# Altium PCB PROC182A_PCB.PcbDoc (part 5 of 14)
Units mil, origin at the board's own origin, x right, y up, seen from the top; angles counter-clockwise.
Board outline 3168.31 x 3700.79 mil, 8 copper layers (Top Layer, L2_GND1, L3_SIG1, L4_PWR1, L5_PWR2, L6_SIG2, L7_GND2, Bottom Layer), stack 58.1 mil thick; 580 components, 391 nets, 8314 pads, 4370 vias.
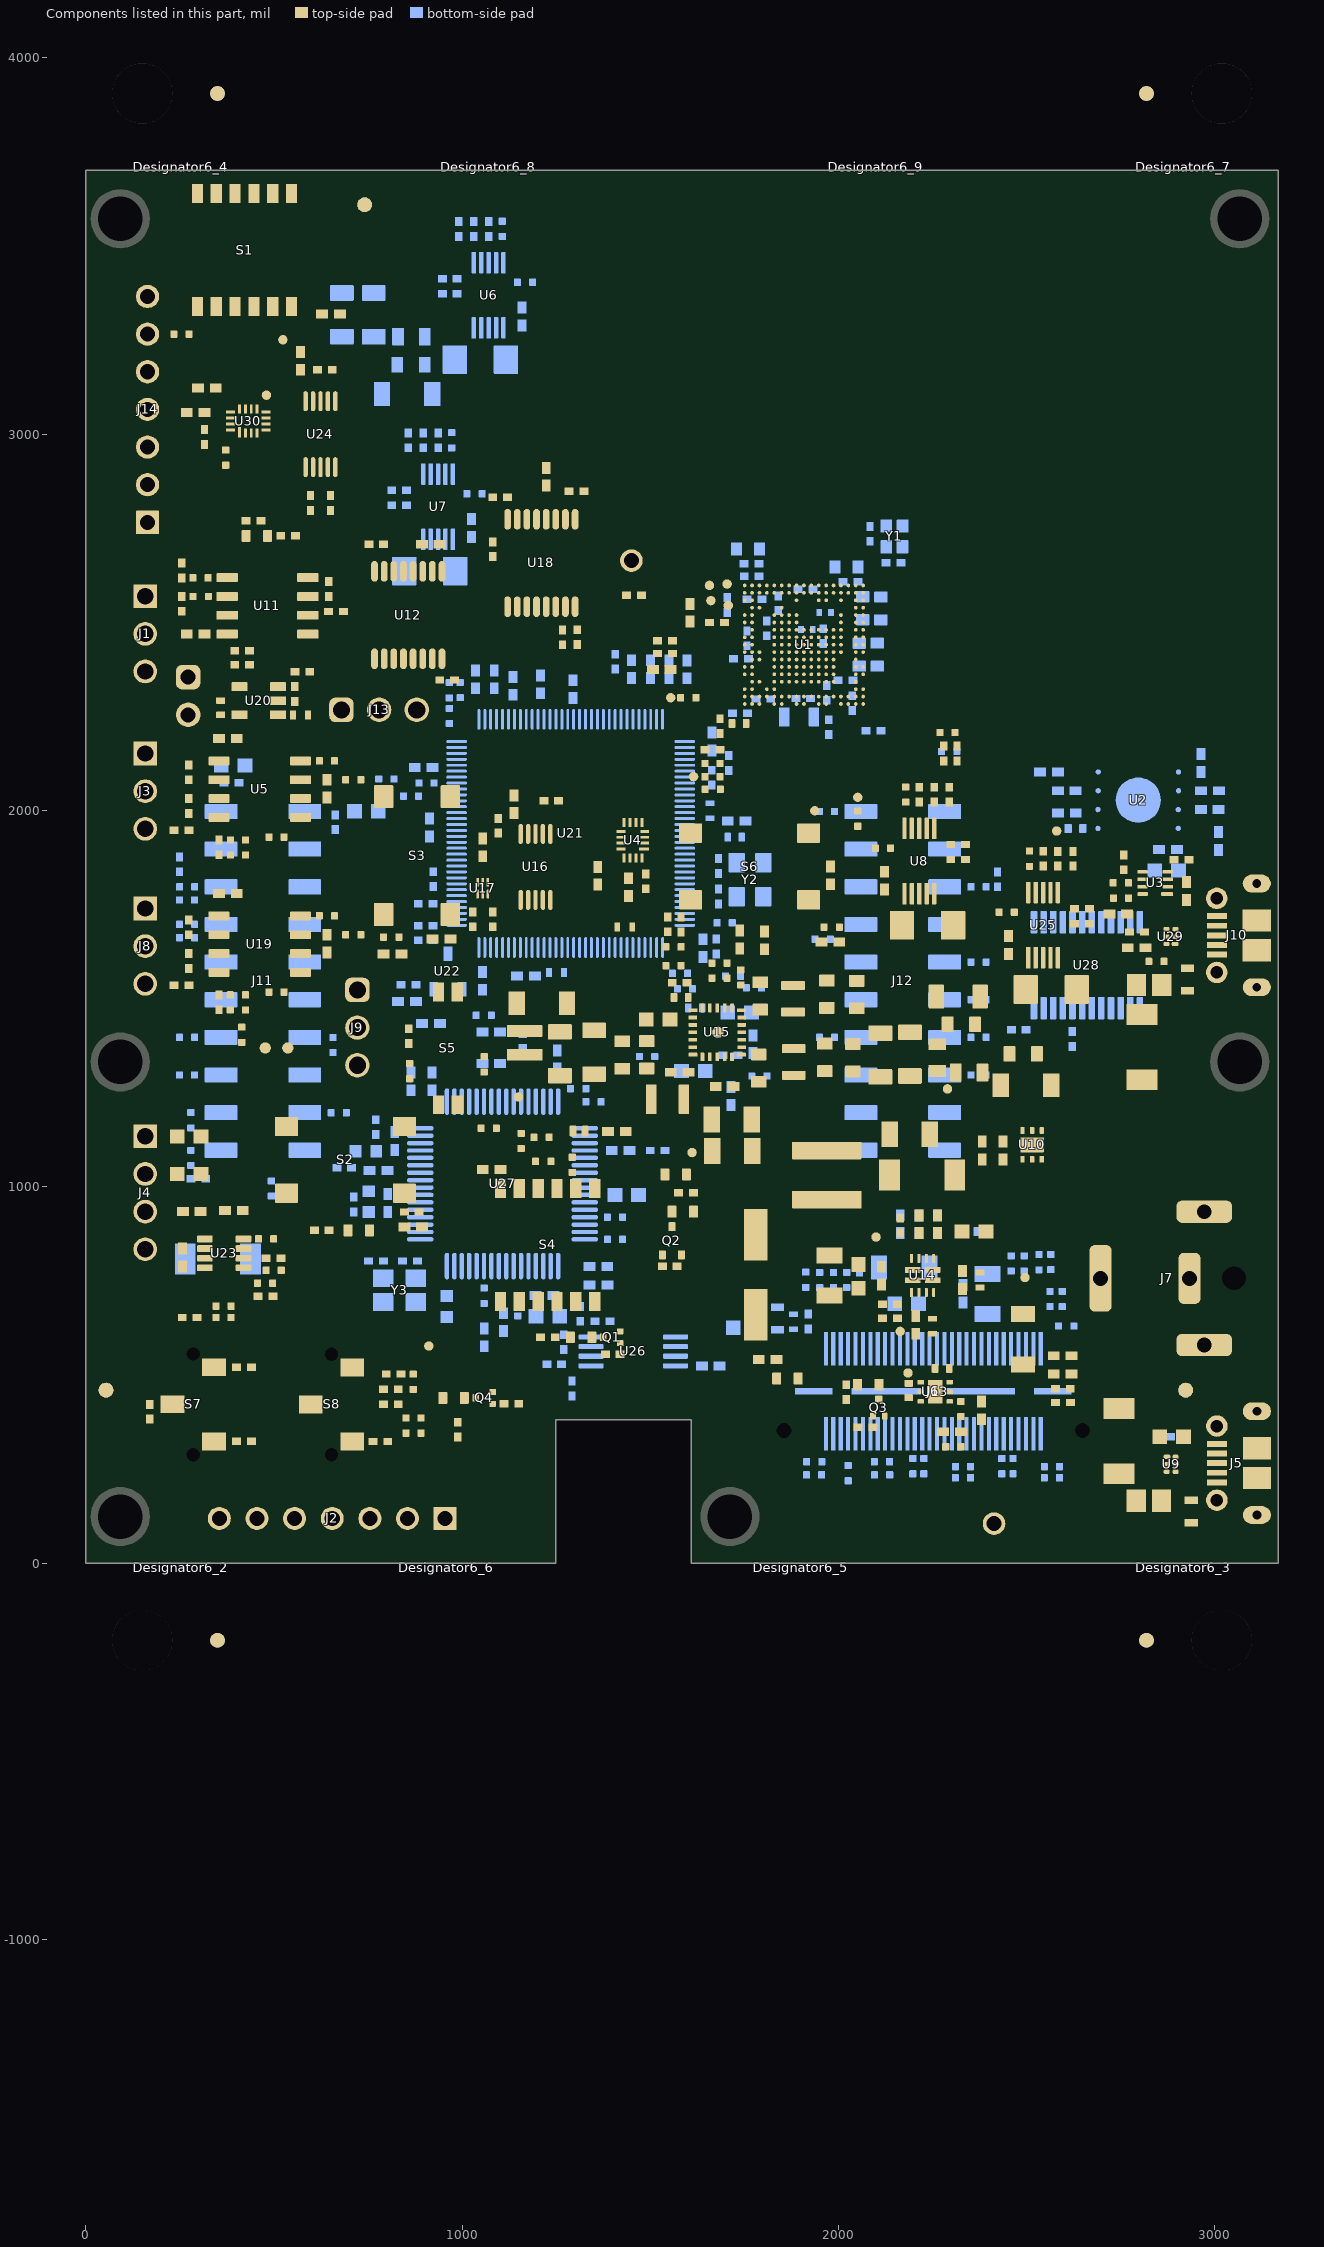
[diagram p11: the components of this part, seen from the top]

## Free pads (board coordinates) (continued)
  round 6 on Mech16: 1(205.76,1382.76) 1(205.76,1382.76) 1(205.76,1414.25) 1(205.76,1414.25) 1(209.78,1279.76) 1(209.78,1279.76) 1(209.78,1311.25) 1(209.78,1311.25) 1(218.77,1080.76) 1(218.77,1080.76) 1(218.77,1112.25) 1(218.77,1112.25) 1(220.77,1182.76) 1(220.77,1182.76) 1(220.77,1214.25) 1(220.77,1214.25) 1(226.29,1382.76) 1(226.29,1414.25) 1(230.3,1279.76) 1(230.3,1311.25) 1(239.3,1080.76) 1(239.3,1112.25) 1(241.3,1182.76) 1(241.3,1214.25) 1(244.29,1382.76) 1(244.29,1414.25) 1(248.3,1279.76) 1(248.3,1311.25) 1(250.83,-300.02) 1(251.83,-250.02) 1(253.83,-248.02) 1(253.83,-248.02) 1(253.83,-200.02) 1(253.83,-200.02) 1(257.3,1080.76) 1(257.3,1112.25) 1(259.3,1182.76) 1(259.3,1214.25) 1(264.82,1382.76) 1(264.82,1382.76) 1(264.82,1414.25) 1(264.82,1414.25) 1(264.83,-300.02) 1(264.83,-300.02) 1(264.83,-189.02) 1(268.83,1279.76) 1(268.83,1279.76) 1(268.83,1311.25) 1(268.83,1311.25) 1(277.82,1080.76) 1(277.82,1080.76) 1(277.82,1112.25) 1(277.82,1112.25) 1(279.82,1182.76) 1(279.82,1182.76) 1(279.82,1214.25) 1(279.82,1214.25) 1(279.83,-285.02) 1(330.55,580.99) 1(330.55,580.99) 1(330.55,601.51) 1(330.55,619.51) 1(330.55,640.04) 1(330.55,640.04) 1(333.83,558.98) 1(362.04,580.99) 1(362.04,580.99) 1(362.04,601.51) 1(362.04,619.51) 1(362.04,640.04) 1(362.04,640.04) 1(365.83,558.98) 1(365.83,558.98) 1(366.83,559.98) 1(434.92,412.58) 1(434.92,412.58) 1(434.92,433.11) 1(434.92,451.11) 1(434.92,471.64) 1(434.92,471.64) 1(434.92,482.58) 1(434.92,482.58) 1(434.92,503.11) 1(434.92,521.11) 1(434.92,541.64) 1(434.92,541.64) 1(466.41,412.58) 1(466.41,412.58) 1(466.41,433.11) 1(466.41,451.11) 1(466.41,471.64) 1(466.41,471.64) 1(466.41,482.58) 1(466.41,482.58) 1(466.41,503.11) 1(466.41,521.11) 1(466.41,541.64) 1(466.41,541.64) 1(559.67,2131.41) 1(559.67,2131.41) 1(559.67,2623.45) 1(559.67,2623.45) 1(567.11,2139.01) 1(567.11,2139.01) 1(567.11,2313.41) 1(567.11,2313.41) 1(567.19,2138.93) 1(567.19,2138.93) 1(567.19,2313.37) 1(567.19,2313.37) 1(606.03,2573.97) 1(606.03,2573.97) 1(607.91,2580.81) 1(607.91,2580.81) 1(608.03,2565.25) 1(608.03,2565.25) 1(608.07,2581.05) 1(608.07,2581.05) 1(608.15,2195.33) 1(608.15,2195.33) 1(608.15,2212.25) 1(608.15,2212.25) 1(610.27,2195.33) 1(610.27,2195.33) 1(610.27,2209.37) 1(610.27,2209.37) 1(610.35,2209.37) 1(610.35,2209.37) 1(611.23,2212.25) 1(611.23,2212.25) 1(611.51,2572.69) 1(611.51,2572.69) 1(612.39,2577.85) 1(612.39,2577.85) 1(612.47,2578.01) 1(612.47,2578.01) 1(612.99,2567.25) 1(612.99,2567.25) 1(613.71,2585.25) 1(613.71,2585.25) 1(615.63,2195.33) 1(615.63,2195.33) 1(616.59,2198.01) 1(616.59,2198.01) 1(616.91,2580.65) 1(616.91,2580.65) 1(617.51,2195.33) 1(617.51,2195.33) 1(617.67,2558.53) 1(617.67,2558.53) 1(619.99,2546.33) 1(619.99,2546.33) 1(621.91,2212.25) 1(621.91,2212.25) 1(622.55,2581.25) 1(622.55,2581.25) 1(622.59,2586.61) 1(622.59,2586.61) 1(622.83,2209.37) 1(622.83,2209.37) 1(622.87,2195.33) 1(622.87,2195.33) 1(622.87,2209.37) 1(622.87,2209.37) 1(624.99,2195.33) 1(624.99,2195.33) 1(624.99,2212.25) 1(624.99,2212.25) 1(625.03,2548.57) 1(625.03,2548.57) 1(626.87,2210.33) 1(626.87,2210.33) 1(626.87,2212.25) 1(626.87,2212.25) 1(632.55,2195.33) 1(632.55,2195.33) 1(632.55,2210.33) 1(632.55,2210.33) 1(632.55,2580.05) 1(632.55,2580.05) 1(632.67,2585.49) 1(632.67,2585.49) 1(634.75,2537.77) 1(634.75,2537.77) 1(634.79,2195.33) 1(634.79,2195.33) 1(634.79,2210.33) 1(634.79,2210.33) 1(640.43,2210.33) 1(640.43,2210.33) 1(640.43,2212.25) 1(640.43,2212.25) 1(640.51,2524.73) 1(640.51,2524.73) 1(641.07,2241.77) 1(641.07,2241.77) 1(641.07,2262.17) 1(641.07,2262.17) 1(641.83,2266.57) 1(641.83,2266.57) 1(643.11,2172.81) 1(643.11,2172.81) 1(643.11,2213.81) 1(643.11,2213.81) 1(643.95,2269.73) 1(643.95,2269.73) 1(644.55,2582.41) 1(644.55,2582.41) 1(644.67,2576.77) 1(644.67,2576.77) 1(646.59,2526.41) 1(646.59,2526.41) 1(647.23,2271.65) 1(647.23,2271.65) 1(647.63,2241.77) 1(647.63,2241.77) 1(647.63,2260.45) 1(647.63,2260.45) 1(649.15,2265.53) 1(649.15,2265.53) 1(650.23,2537.73) 1(650.23,2537.73) 1(650.71,2172.81) 1(650.71,2172.81) 1(650.71,2176.05) 1(650.71,2176.05) 1(650.83,2176.05) 1(650.83,2176.05) 1(651.03,2188.25) 1(651.03,2188.25) 1(651.03,2200.85) 1(651.03,2200.85) 1(651.03,2213.81) 1(651.03,2213.81) 1(651.13,-803.95) 1(651.15,2200.85) 1(651.15,2200.85) 1(651.23,2183.85) 1(651.23,2183.85) 1(651.23,2192.69) 1(651.23,2192.69) 1(651.63,2272.29) 1(651.63,2272.29) 1(651.83,2180.65) 1(651.83,2180.65) 1(651.83,2195.85) 1(651.83,2195.85) 1(653.11,2178.73) 1(653.11,2178.73) 1(653.11,2197.77) 1(653.11,2197.77) 1(653.43,2267.13) 1(653.43,2267.13) 1(653.83,2172.97) 1(653.83,2172.97) 1(653.99,2203.61) 1(653.99,2203.61) 1(655.27,2178.09) 1(655.27,2178.09) 1(655.27,2198.41) 1(655.27,2198.41) 1(656.43,2266.53) 1(656.43,2266.53) 1(656.63,2548.89) 1(656.63,2548.89) 1(656.91,2270.97) 1(656.91,2270.97) 1(657.35,2178.73) 1(657.35,2178.73) 1(657.35,2197.77) 1(657.35,2197.77) 1(657.83,2171.97) 1(657.83,2171.97) 1(657.83,2204.49) 1(657.83,2204.49) 1(657.87,2577.61) 1(657.87,2577.61) 1(658.51,2571.57) 1(658.51,2571.57) 1(658.63,2180.65) 1(658.63,2180.65) 1(658.63,2195.85) 1(658.63,2195.85) 1(658.67,2264.85) 1(658.67,2264.85) 1(659.23,2183.81) 1(659.23,2183.81) 1(659.23,2192.69) 1(659.23,2192.69) 1(659.39,2188.25) 1(659.39,2188.25) 1(660.11,2262.37) 1(660.11,2262.37) 1(660.3,-818.55) 1(660.3,-813.12) 1(660.3,-813.12) 1(660.51,2267.57) 1(660.51,2267.57) 1(660.63,2241.77) 1(660.63,2241.77) 1(660.63,2259.29) 1(660.63,2259.29) 1(660.63,2267.57) 1(660.63,2267.57) 1(660.63,2282.81) 1(660.63,2282.81) 1(662.07,2172.89) 1(662.07,2172.89) 1(662.07,2203.57) 1(662.07,2203.57) 1(664.79,2558.37) 1(664.79,2558.37) 1(665.03,2175.81) 1(665.03,2175.81) 1(665.03,2200.69) 1(665.03,2200.69) 1(666.75,2180.85) 1(666.75,2180.85) 1(666.75,2195.65) 1(666.75,2195.65) 1(666.83,2502.89) 1(666.83,2502.89) 1(667.19,2241.77) 1(667.19,2241.77) 1(667.19,2282.81) 1(667.19,2282.81) 1(667.31,2188.25) 1(667.31,2188.25) 1(671.83,2172.81) 1(671.83,2172.81) 1(672.19,2571.25) 1(672.19,2571.25) 1(672.43,2241.81) 1(672.43,2241.81) 1(672.43,2246.89) 1(672.43,2246.89) 1(672.43,2266.61) 1(672.43,2266.61) 1(672.43,2271.49) 1(672.43,2271.49) 1(672.59,2175.37) 1(672.59,2175.37) 1(672.79,2178.77) 1(672.79,2178.77) 1(672.79,2195.05) 1(672.79,2195.05) 1(673.19,2198.85) 1(673.19,2198.85) 1(673.63,2564.61) 1(673.63,2564.61) 1(674.87,2201.85) 1(674.87,2201.85) 1(675.19,2246.65) 1(675.19,2246.65) 1(676.67,2241.49) 1(676.67,2241.49) 1(677.87,2247.69) 1(677.87,2247.69) 1(678.27,2203.81) 1(678.27,2203.81) 1(678.35,2250.73) 1(678.35,2250.73) 1(678.35,2266.61) 1(678.35,2266.61) 1(678.35,2271.49) 1(678.35,2271.49) 1(678.35,2280.41) 1(678.35,2280.41) 1(679.39,2172.81) 1(679.39,2172.81) 1(680.39,2176.01) 1(680.39,2176.01) 1(680.39,2182.17) 1(680.39,2182.17) 1(680.39,2188.25) 1(680.39,2188.25) 1(680.39,2195.33) 1(680.39,2195.33) 1(680.47,2176.01) 1(680.47,2176.01) 1(680.83,2241.97) 1(680.83,2241.97) 1(681.07,2192.97) 1(681.07,2192.97) 1(681.23,2198.09) 1(681.23,2198.09) 1(682.03,2178.49) 1(682.03,2178.49) 1(683.31,2243.45) 1(683.31,2243.45) 1(683.47,2497.61) 1(683.47,2497.61) 1(683.51,2191.69) 1(683.51,2191.69) 1(683.67,2172.81) 1(683.67,2172.81) 1(683.75,2186.69) 1(683.75,2186.69) 1(683.99,2204.49) 1(683.99,2204.49) 1(684.03,2199.09) 1(684.03,2199.09) 1(684.51,2245.81) 1(684.51,2245.81) 1(684.87,2249.09) 1(684.87,2249.09) 1(684.87,2266.61) 1(684.87,2266.61) 1(684.87,2271.49) 1(684.87,2271.49) 1(684.87,2280.41) 1(684.87,2280.41) 1(685.27,2177.37) 1(685.27,2177.37) 1(686.79,2198.01) 1(686.79,2198.01) 1(686.79,2510.65) 1(686.79,2510.65) 1(687.07,2563.57) 1(687.07,2563.57) 1(687.23,2184.97) 1(687.23,2184.97) 1(687.55,2178.65) 1(687.55,2178.65) 1(687.71,2194.25) 1(687.71,2194.25) 1(687.71,2195.09) 1(687.71,2195.09) 1(688.03,2190.49) 1(688.03,2190.49) 1(688.23,2181.69) 1(688.23,2181.69) 1(688.23,2204.01) 1(688.23,2204.01) 1(688.35,2171.97) 1(688.35,2171.97) 1(689.83,2266.61) 1(689.83,2266.61) 1(689.83,2271.49) 1(689.83,2271.49) 1(691.55,2189.17) 1(691.55,2189.17) 1(691.67,2202.41) 1(691.67,2202.41) 1(691.87,2172.77) 1(691.87,2172.77) 1(693.95,2187.29) 1(693.95,2187.29) 1(693.99,2199.49) 1(693.99,2199.49) 1(694.15,2174.85) 1(694.15,2174.85) 1(694.15,2523.77) 1(694.15,2523.77) 1(694.47,2241.77) 1(694.47,2241.77) 1(694.47,2271.49) 1(694.47,2271.49) 1(694.47,2276.61) 1(694.47,2276.61) 1(694.47,2282.81) 1(694.47,2282.81) 1(694.83,2194.25) 1(694.83,2194.25) 1(694.83,2194.97) 1(694.83,2194.97) 1(695.39,2184.57) 1(695.39,2184.57) 1(695.43,2177.73) 1(695.43,2177.73) 1(695.83,567.22) 1(695.83,567.22) 1(695.83,575.98) 1(695.83,2180.85) 1(695.83,2180.85) 1(696.15,2483.29) 1(696.15,2483.29) 1(696.75,2201.53) 1(696.75,2201.53) 1(697.35,2206.05) 1(697.35,2206.05) 1(697.71,2196.01) 1(697.71,2196.01) 1(699.23,2209.97) 1(699.23,2209.97) 1(700.19,2480.93) 1(700.19,2480.93) 1(700.35,2192.17) 1(700.35,2192.17) 1(701.03,2241.77) 1(701.03,2241.77) 1(701.03,2271.49) 1(701.03,2271.49) 1(701.03,2276.61) 1(701.03,2276.61) 1(701.03,2282.81) 1(701.03,2282.81) 1(702.15,2554.81) 1(702.15,2554.81) 1(702.71,2212.77) 1(702.71,2212.77) 1(702.92,560.13) 1(703.07,2461.61) 1(703.07,2461.61) 1(703.87,2534.53) 1(703.87,2534.53) 1(704.47,2189.93) 1(704.47,2189.93) 1(705.03,2201.41) 1(705.03,2201.41) 1(705.95,2271.49) 1(705.95,2271.49) 1(706.03,2508.01) 1(706.03,2508.01) 1(706.35,2206.09) 1(706.35,2206.09) 1(706.55,2196.77) 1(706.55,2196.77) 1(707.19,2462.29) 1(707.19,2462.29) 1(707.91,1266.46) 1(707.91,1266.46) 1(707.91,1266.46) 1(708.03,2213.81) 1(708.03,2213.81) 1(709.79,2189.17) 1(709.79,2189.17) 1(710.55,2195.25) 1(710.55,2195.25) 1(710.79,2207.73) 1(710.79,2207.73) 1(711.83,2516.53) 1(711.83,2516.53) 1(712.59,2271.49) 1(712.59,2271.49) 1(713.59,2541.05) 1(713.59,2541.05) 1(714.23,2172.81) 1(714.23,2172.81) 1(714.23,2189.17) 1(714.23,2189.17) 1(714.23,2195.25) 1(714.23,2195.25) 1(714.23,2207.73) 1(714.23,2207.73) 1(714.27,2540.49) 1(714.27,2540.49) 1(715.23,2241.77) 1(715.23,2241.77) 1(716.23,2478.45) 1(716.23,2478.45) 1(716.41,1257.96) 1(716.41,1257.96) 1(716.41,1274.96) 1(716.41,1274.96) 1(716.95,2545.13) 1(716.95,2545.13) 1(718.47,2444.09) 1(718.47,2444.09) 1(718.63,2249.29) 1(718.63,2249.29) 1(718.75,2249.29) 1(718.75,2249.29) 1(718.93,-820.55) 1(718.93,-809.55) 1(718.93,-809.55) 1(718.93,-809.55) 1(721.83,2470.01) 1(721.83,2470.01) 1(721.95,2241.77) 1(721.95,2241.77) 1(722.51,2172.81) 1(722.51,2172.81) 1(722.51,2213.81) 1(722.51,2213.81) 1(723.75,2444.69) 1(723.75,2444.69) 1(724.11,2271.49) 1(724.11,2271.49) 1(727.47,2263.85) 1(727.47,2263.85) 1(727.59,2263.85) 1(727.59,2263.85) 1(729.71,2172.81) 1(729.71,2172.81) 1(729.71,2195.73) 1(729.71,2195.73) 1(730.23,2199.65) 1(730.23,2199.65) 1(730.71,2271.49) 1(730.71,2271.49) 1(731.15,2534.77) 1(731.15,2534.77) 1(731.79,2202.41) 1(731.79,2202.41) 1(733.07,2241.77) 1(733.07,2241.77) 1(734.27,2204.01) 1(734.27,2204.01) 1(734.83,2531.89) 1(734.83,2531.89) 1(735.95,2436.17) 1(735.95,2436.17) 1(736.27,2249.29) 1(736.27,2249.29) 1(736.39,2249.29) 1(736.39,2249.29) 1(737.59,2204.49) 1(737.59,2204.49) 1(737.63,2172.81) 1(737.63,2172.81) 1(737.63,2194.09) 1(737.63,2194.09) 1(737.71,2430.69) 1(737.71,2430.69) 1(737.87,2450.13) 1(737.87,2450.13) 1(738.43,2197.41) 1(738.43,2197.41) 1(738.67,2456.37) 1(738.67,2456.37) 1(739.11,2444.41) 1(739.11,2444.41) 1(739.95,2241.77) 1(739.95,2241.77) 1(741.03,2198.41) 1(741.03,2198.41) 1(741.71,2450.29) 1(741.71,2450.29) 1(741.75,2439.65) 1(741.75,2439.65) 1(742.03,2203.53) 1(742.03,2203.53) 1(742.19,2271.49) 1(742.19,2271.49) 1(742.23,2462.61) 1(742.23,2462.61) 1(742.27,2462.65) 1(742.27,2462.65) 1(742.35,2455.25) 1(742.35,2455.25) 1(742.47,2536.97) 1(742.47,2536.97) 1(742.71,2445.73) 1(742.71,2445.73) 1(743.19,2437.69) 1(743.19,2437.69) 1(743.23,2517.77) 1(743.23,2517.77) 1(744.15,2197.17) 1(744.15,2197.17) 1(744.79,2441.93) 1(744.79,2441.93) 1(745.11,2200.57) 1(745.11,2200.57) 1(745.19,2460.17) 1(745.19,2460.17) 1(745.23,2172.81) 1(745.23,2172.81) 1(745.23,2193.29) 1(745.23,2193.29) 1(745.23,2200.57) 1(745.23,2200.57) 1(745.23,2213.81) 1(745.23,2213.81) 1(745.31,2460.33) 1(745.31,2460.33) 1(745.47,2467.37) 1(745.47,2467.37) 1(746.27,2433.49) 1(746.27,2433.49) 1(746.27,2439.93) 1(746.27,2439.93) 1(749.15,2271.49) 1(749.15,2271.49) 1(750.15,2428.41) 1(750.15,2428.41) 1(751.55,2432.85) 1(751.55,2432.85) 1(752.51,2477.69) 1(752.51,2477.69) 1(752.99,2515.81) 1(752.99,2515.81) 1(753.15,2172.81) 1(753.15,2172.81) 1(753.15,2213.81) 1(753.15,2213.81) 1(753.87,2536.33) 1(753.87,2536.33) 1(754.75,2532.21) 1(754.75,2532.21) 1(755.71,2475.61) 1(755.71,2475.61) 1(756.15,2421.41) 1(756.15,2421.41) 1(757.11,2484.49) 1(757.11,2484.49) 1(757.83,2184.61) 1(757.83,2184.61) 1(757.83,2192.57) 1(757.83,2192.57) 1(758.35,2424.45) 1(758.35,2424.45) 1(758.47,2179.25) 1(758.47,2179.25) 1(758.51,2197.49) 1(758.51,2197.49) 1(760.23,2482.25) 1(760.23,2482.25) 1(760.55,2175.25) 1(760.55,2175.25) 1(760.63,2201.25) 1(760.63,2201.25) 1(760.91,2453.17) 1(760.91,2453.17) 1(764.03,2455.37) 1(764.03,2455.37) 1(764.07,2203.65) 1(764.07,2203.65) 1(764.07,2494.77) 1(764.07,2494.77) 1(764.19,2172.81) 1(764.19,2172.81) 1(765.03,2533.29) 1(765.03,2533.29) 1(765.39,2184.61) 1(765.39,2184.61) 1(765.39,2192.57) 1(765.39,2192.57) 1(766.07,2196.77) 1(766.07,2196.77) 1(766.31,2179.13) 1(766.31,2179.13) 1(767.31,2499.45) 1(767.31,2499.45) 1(767.35,2499.49) 1(767.35,2499.49) 1(768.47,2250.61) 1(768.47,2250.61) 1(768.87,2204.49) 1(768.87,2204.49) 1(768.95,2198.77) 1(768.95,2198.77) 1(769.23,2177.37) 1(769.23,2177.37) 1(769.31,2254.29) 1(769.31,2254.29) 1(769.47,2263.17) 1(769.47,2263.17) 1(769.59,2171.97) 1(769.59,2171.97) 1(769.71,2246.13) 1(769.71,2246.13) 1(770.67,2497.65) 1(770.67,2497.65) 1(770.87,2267.37) 1(770.87,2267.37) 1(771.31,2198.13) 1(771.31,2198.13) 1(771.43,2178.01) 1(771.43,2178.01) 1(771.51,2256.77) 1(771.51,2256.77) 1(771.83,2505.13) 1(771.83,2505.13) 1(772.71,2179.93) 1(772.71,2179.93) 1(772.71,2196.17) 1(772.71,2196.17) 1(772.79,2243.17) 1(772.79,2243.17) 1(773.35,2183.29) 1(773.35,2183.29) 1(773.35,2192.85) 1(773.35,2192.85) 1(773.51,2188.17) 1(773.51,2188.17) 1(773.67,2270.21) 1(773.67,2270.21) 1(773.95,2203.77) 1(773.95,2203.77) 1(774.23,2502.13) 1(774.23,2502.13) 1(774.55,2258.33) 1(774.55,2258.33) 1(774.79,2172.77) 1(774.79,2172.77) 1(775.03,2250.05) 1(775.03,2250.05) 1(775.63,2248.01) 1(775.63,2248.01) 1(775.83,2528.45) 1(775.83,2528.45) 1(775.95,2252.13) 1(775.95,2252.13) 1(776.27,2263.17) 1(776.27,2263.17) 1(776.35,2478.33) 1(776.35,2478.33) 1(776.59,2478.21) 1(776.59,2478.21) 1(777.11,2241.49) 1(777.11,2241.49) 1(777.19,2523.29) 1(777.19,2523.29) 1(777.31,2508.17) 1(777.31,2508.17) 1(777.35,2246.85) 1(777.35,2246.85) 1(777.47,2271.81) 1(777.47,2271.81) 1(777.79,2437.05) 1(777.79,2437.05) 1(777.87,2481.81) 1(777.87,2481.81) 1(777.91,2201.13) 1(777.91,2201.13) 1(778.07,2259.29) 1(778.07,2259.29) 1(778.07,2481.73) 1(778.07,2481.73) 1(778.15,2253.41) 1(778.15,2253.41) 1(778.43,2266.29) 1(778.43,2266.29) 1(778.47,2175.45) 1(778.47,2175.45) 1(778.59,2504.53) 1(778.59,2504.53) 1(779.55,2246.29) 1(779.55,2246.29) 1(780.51,2196.13) 1(780.51,2196.13) 1(780.71,2180.49) 1(780.71,2180.49) 1(781.23,2254.25) 1(781.23,2254.25) 1(781.43,2188.25) 1(781.43,2188.25) 1(781.63,2246.13) 1(781.63,2246.13) 1(781.63,2260.05) 1(781.63,2260.05) 1(781.75,2240.97) 1(781.75,2240.97) 1(781.87,2272.29) 1(781.87,2272.29) 1(782.31,2267.13) 1(782.31,2267.13) 1(782.39,2458.25) 1(782.39,2458.25) 1(783.11,2509.09) 1(783.11,2509.09) 1(783.23,2505.29) 1(783.23,2505.29) 1(784.71,2260.89) 1(784.71,2260.89) 1(784.75,2255.01) 1(784.75,2255.01) 1(785.43,2450.85) 1(785.43,2450.85) 1(785.75,2266.57) 1(785.75,2266.57) 1(785.99,2522.33) 1(785.99,2522.33) 1(786.07,2271.89) 1(786.07,2271.89) 1(786.11,2172.81) 1(786.11,2172.81) 1(786.11,2195.73) 1(786.11,2195.73) 1(786.19,2247.29) 1(786.19,2247.29) 1(786.23,2463.85) 1(786.23,2463.85) 1(786.63,2199.65) 1(786.63,2199.65) 1(786.91,2262.13) 1(786.91,2262.13) 1(786.95,2241.61) 1(786.95,2241.61) 1(787.51,2504.69) 1(787.51,2504.69) 1(787.71,2264.09) 1(787.71,2264.09) 1(788.19,2202.41) 1(788.19,2202.41) 1(788.27,2255.97) 1(788.27,2255.97) 1(788.35,2251.29) 1(788.35,2251.29) 1(788.35,2251.33) 1(788.35,2251.33) 1(788.43,2453.21) 1(788.43,2453.21) 1(788.51,2508.41) 1(788.51,2508.41) 1(789.03,2418.17) 1(789.03,2418.17) 1(789.59,2515.09) 1(789.59,2515.09) 1(789.87,2472.45) 1(789.87,2472.45) 1(789.91,2504.09) 1(789.91,2504.09) 1(790.11,2270.49) 1(790.11,2270.49) 1(790.63,2204.01) 1(790.63,2204.01) 1(790.87,2507.81) 1(790.87,2507.81) 1(791.11,2243.53) 1(791.11,2243.53) 1(791.31,2257.53) 1(791.31,2257.53) 1(791.47,2475.93) 1(791.47,2475.93) 1(791.99,2420.77) 1(791.99,2420.77) 1(793.11,2267.85) 1(793.11,2267.85) 1(793.47,2260.01) 1(793.47,2260.01) 1(793.87,2246.73) 1(793.87,2246.73) 1(793.95,2204.49) 1(793.95,2204.49) 1(794.03,2172.81) 1(794.03,2172.81) 1(794.03,2194.09) 1(794.03,2194.09) 1(794.27,2263.77) 1(794.27,2263.77) 1(794.83,2197.41) 1(794.83,2197.41) 1(794.95,2251.33) 1(794.95,2251.33) 1(795.35,2515.49) 1(795.35,2515.49) 1(795.91,2506.45) 1(795.91,2506.45) 1(797.03,2241.77) 1(797.03,2241.77) 1(797.43,2198.41) 1(797.43,2198.41) 1(798.15,2271.49) 1(798.15,2271.49) 1(798.43,2501.77) 1(798.43,2501.77) 1(798.51,2203.45) 1(798.51,2203.45) 1(800.51,2197.17) 1(800.51,2197.17) 1(801.63,2172.81) 1(801.63,2172.81) 1(801.63,2193.29) 1(801.63,2193.29) 1(801.83,2200.09) 1(801.83,2200.09) 1(801.95,2200.09) 1(801.95,2200.09) 1(801.95,2203.69) 1(801.95,2203.69) 1(801.95,2432.45) 1(801.95,2432.45) 1(802.03,2504.73) 1(802.03,2504.73) 1(803.67,2508.41) 1(803.67,2508.41) 1(804.67,2435.17) 1(804.67,2435.17) 1(804.91,2465.49) 1(804.91,2465.49) 1(805.03,2241.77) 1(805.03,2241.77) 1(805.15,2479.57) 1(805.15,2479.57) 1(805.83,2483.29) 1(805.83,2483.29) 1(806.19,2271.49) 1(806.19,2271.49) 1(806.67,2468.89) 1(806.67,2468.89) 1(806.95,2406.33) 1(806.95,2406.33) 1(808.75,2498.53) 1(808.75,2498.53) 1(809.51,2260.57) 1(809.51,2260.57) 1(809.55,2172.81) 1(809.55,2172.81) 1(809.55,2203.69) 1(809.55,2203.69) 1(810.71,2501.73) 1(810.71,2501.73) 1(814.11,2256.21) 1(814.11,2256.21) 1(815.35,2172.81) 1(815.35,2172.81) 1(815.35,2203.69) 1(815.35,2203.69) 1(818.03,2241.77) 1(818.03,2241.77) 1(818.03,2252.41) 1(818.03,2252.41) 1(818.03,2259.49) 1(818.03,2259.49) 1(818.03,2282.81) 1(818.03,2282.81) 1(818.95,2391.53) 1(818.95,2391.53) 1(820.87,2416.17) 1(820.87,2416.17) 1(821.39,2457.01) 1(821.39,2457.01) 1(822.91,2172.81) 1(822.91,2172.81) 1(822.91,2176.41) 1(822.91,2176.41) 1(822.91,2393.49) 1(822.91,2393.49) 1(823.03,2176.41) 1(823.03,2176.41) 1(823.11,2474.41) 1(823.11,2474.41) 1(823.27,2183.17) 1(823.27,2183.17) 1(823.27,2203.69) 1(823.27,2203.69) 1(823.27,2419.17) 1(823.27,2419.17) 1(823.31,2460.33) 1(823.31,2460.33) 1(824.27,2478.05) 1(824.27,2478.05) 1(824.35,2179.33) 1(824.35,2179.33) 1(824.55,2282.81) 1(824.55,2282.81) 1(824.59,2241.77) 1(824.59,2241.77) 1(824.59,2282.81) 1(824.59,2282.81) 1(826.35,2173.05) 1(826.35,2173.05) 1(827.47,2178.09) 1(827.47,2178.09) 1(828.15,2265.81) 1(828.15,2265.81) 1(828.15,2272.13) 1(828.15,2272.13) 1(829.95,1266.46) 1(830.07,2179.09) 1(830.07,2179.09) 1(830.59,2272.29) 1(830.59,2272.29) 1(830.87,2182.37) 1(830.87,2182.37) 1(830.87,2203.69) 1(830.87,2203.69) 1(830.91,2171.97) 1(830.91,2171.97) 1(830.95,2266.09) 1(830.95,2266.09) 1(833.59,2271.73) 1(833.59,2271.73) 1(834.11,2265.41) 1(834.11,2265.41) 1(834.23,2172.49) 1(834.23,2172.49) 1(836.19,2270.21) 1(836.19,2270.21) 1(836.67,2263.45) 1(836.67,2263.45) 1(836.71,2174.09) 1(836.71,2174.09) 1(836.91,2379.53) 1(836.91,2379.53) 1(838.19,2268.09) 1(838.19,2268.09) 1(838.27,2176.85) 1(838.27,2176.85) 1(838.39,2260.29) 1(838.39,2260.29) 1(838.79,2180.77) 1(838.79,2180.77) 1(838.79,2203.69) 1(838.79,2203.69) 1(838.99,2241.77) 1(838.99,2241.77) 1(838.99,2255.93) 1(838.99,2255.93) 1(839.03,2446.73) 1(839.03,2446.73) 1(839.31,2265.73) 1(839.31,2265.73) 1(839.39,2265.73) 1(839.39,2265.73) 1(839.39,2271.49) 1(839.39,2271.49) 1(840.19,2382.09) 1(840.19,2382.09) 1(841.11,2449.93) 1(841.11,2449.93) 1(842.87,2465.41) 1(842.87,2465.41) 1(843.03,2401.37) 1(843.03,2401.37) 1(844.03,2172.81) 1(844.03,2172.81) 1(844.43,2468.89) 1(844.43,2468.89) 1(844.83,2175.37) 1(844.83,2175.37) 1(844.99,2178.77) 1(844.99,2178.77) 1(844.99,2195.05) 1(844.99,2195.05) 1(845.07,2404.61) 1(845.07,2404.61) 1(845.43,2198.85) 1(845.43,2198.85) 1(845.55,2241.77) 1(845.55,2241.77) 1(845.55,2271.49) 1(845.55,2271.49) 1(847.07,2201.85) 1(847.07,2201.85) 1(850.51,2203.81) 1(850.51,2203.81) 1(851.63,2172.81) 1(851.63,2172.81) 1(851.63,2256.65) 1(851.63,2256.65) 1(852.59,2176.01) 1(852.59,2176.01) 1(852.59,2182.17) 1(852.59,2182.17) 1(852.59,2188.25) 1(852.59,2188.25) 1(852.59,2195.33) 1(852.59,2195.33) 1(852.63,2250.37) 1(852.63,2250.37) 1(852.63,2262.93) 1(852.63,2262.93) 1(852.71,2176.01) 1(852.71,2176.01) 1(853.31,2192.97) 1(853.31,2192.97) 1(853.43,2198.09) 1(853.43,2198.09) 1(854.23,2178.49) 1(854.23,2178.49) 1(855.55,2245.37) 1(855.55,2245.37) 1(855.55,2267.89) 1(855.55,2267.89) 1(855.75,2191.69) 1(855.75,2191.69) 1(855.91,2172.81) 1(855.91,2172.81) 1(855.99,2186.69) 1(855.99,2186.69) 1(856.23,2204.49) 1(856.23,2204.49) 1(856.27,2199.09) 1(856.27,2199.09) 1(856.91,2368.65) 1(856.91,2368.65) 1(857.47,2177.37) 1(857.47,2177.37) 1(857.51,2434.33) 1(857.51,2434.33) 1(858.15,2256.65) 1(858.15,2256.65) 1(858.63,2252.85) 1(858.63,2252.85) 1(858.63,2260.45) 1(858.63,2260.45) 1(859.03,2198.01) 1(859.03,2198.01) 1(859.11,2371.81) 1(859.11,2371.81) 1(859.43,2184.97) 1(859.43,2184.97) 1(859.79,2178.65) 1(859.79,2178.65) 1(859.79,2437.41) 1(859.79,2437.41) 1(859.95,2194.25) 1(859.95,2194.25) 1(859.95,2195.09) 1(859.95,2195.09) 1(860.19,2249.45) 1(860.19,2249.45) 1(860.19,2263.81) 1(860.19,2263.81) 1(860.23,2190.49) 1(860.23,2190.49) 1(860.23,2242.13) 1(860.23,2242.13) 1(860.23,2271.13) 1(860.23,2271.13) 1(860.43,2204.01) 1(860.43,2204.01) 1(860.47,2181.69) 1(860.47,2181.69) 1(860.59,2171.97) 1(860.59,2171.97) 1(862.79,2247.05) 1(862.79,2247.05) 1(862.79,2266.21) 1(862.79,2266.21) 1(863.71,2453.01) 1(863.71,2453.01) 1(863.75,2189.17) 1(863.75,2189.17) 1(863.91,2202.41) 1(863.91,2202.41) 1(864.11,2172.77) 1(864.11,2172.77) 1(865.71,2456.25) 1(865.71,2456.25) 1(866.19,2187.29) 1(866.19,2187.29) 1(866.23,2199.49) 1(866.23,2199.49) 1(866.39,2174.85) 1(866.39,2174.85) 1(866.59,2240.97) 1(866.59,2240.97) 1(866.59,2246.13) 1(866.59,2246.13) 1(866.59,2267.13) 1(866.59,2267.13) 1(866.59,2272.29) 1(866.59,2272.29) 1(867.07,2194.25) 1(867.07,2194.25) 1(867.07,2194.97) 1(867.07,2194.97) 1(867.59,2184.57) 1(867.59,2184.57) 1(867.67,2177.73) 1(867.67,2177.73) 1(868.07,2180.85) 1(868.07,2180.85) 1(869.15,2387.45) 1(869.15,2387.45) 1(870.39,2247.05) 1(870.39,2247.05) 1(870.39,2266.21) 1(870.39,2266.21) 1(870.83,2390.89) 1(870.83,2390.89) 1(870.99,2172.81) 1(870.99,2172.81) 1(870.99,2179.57) 1(870.99,2179.57) 1(872.95,2242.13) 1(872.95,2242.13) 1(872.95,2271.13) 1(872.95,2271.13) 1(873.03,2249.45) 1(873.03,2249.45) 1(873.03,2263.81) 1(873.03,2263.81) 1(874.55,2252.85) 1(874.55,2252.85) 1(874.55,2260.45) 1(874.55,2260.45) 1(875.07,2256.65) 1(875.07,2256.65) 1(876.55,2419.49) 1(876.55,2419.49) 1(877.67,2245.37) 1(877.67,2245.37) 1(877.67,2267.89) 1(877.67,2267.89) 1(879.03,2422.41) 1(879.03,2422.41) 1(879.35,2358.69) 1(879.35,2358.69) 1(879.99,2362.57) 1(879.99,2362.57) 1(880.59,2250.37) 1(880.59,2250.37) 1(880.59,2262.93) 1(880.59,2262.93) 1(881.59,2256.65) 1(881.59,2256.65) 1(883.63,2282.81) 1(883.63,2282.81) 1(884.95,2437.49) 1(884.95,2437.49) 1(885.63,2179.57) 1(885.63,2179.57) 1(885.63,2213.81) 1(885.63,2213.81) 1(887.35,2440.49) 1(887.35,2440.49) 1(890.91,2282.81) 1(890.91,2282.81) 1(893.91,2172.81) 1(893.91,2172.81) 1(893.91,2213.81) 1(893.91,2213.81) 1(894.95,2241.77) 1(894.95,2241.77) 1(895.27,2372.29) 1(895.27,2372.29) 1(895.79,2401.93) 1(895.79,2401.93) 1(897.95,2374.93) 1(897.95,2374.93) 1(898.47,2404.65) 1(898.47,2404.65) 1(898.55,2251.41) 1(898.55,2251.41) 1(898.67,2251.41) 1(898.67,2251.41) 1(900.67,2362.17) 1(900.67,2362.17) 1(902.07,2368.13) 1(902.07,2368.13) 1(902.23,2241.77) 1(902.23,2241.77) 1(903.07,2354.05) 1(903.07,2354.05) 1(904.55,2349.53) 1(904.55,2349.53) 1(905.63,2359.85) 1(905.63,2359.85) 1(906.71,2282.81) 1(906.71,2282.81) 1(906.75,2418.49) 1(906.75,2418.49) 1(907.07,2351.33) 1(907.07,2351.33) 1(907.11,2348.69) 1(907.11,2348.69) 1(910.23,2420.41) 1(910.23,2420.41) 1(910.47,2273.13) 1(910.47,2273.13) 1(910.59,2273.13) 1(910.59,2273.13) 1(912.71,2367.21) 1(912.71,2367.21) 1(914.07,2282.81) 1(914.07,2282.81) 1(914.91,2172.81) 1(914.91,2172.81) 1(914.91,2213.81) 1(914.91,2213.81) 1(914.99,2381.29) 1(914.99,2381.29) 1(917.71,2361.01) 1(917.71,2361.01) 1(917.91,2383.77) 1(917.91,2383.77) 1(918.95,2241.77) 1(918.95,2241.77) 1(922.35,2251.41) 1(922.35,2251.41) 1(922.47,2251.41) 1(922.47,2251.41) 1(923.19,2172.81) 1(923.19,2172.81) 1(923.19,2213.81) 1(923.19,2213.81) 1(926.39,2241.77) 1(926.39,2241.77) 1(926.59,2397.69) 1(926.59,2397.69) 1(927.67,2207.05) 1(927.67,2207.05) 1(927.67,2213.81) 1(927.67,2213.81) 1(928.91,2361.01) 1(928.91,2361.01) 1(929.87,2282.81) 1(929.87,2282.81) 1(930.99,2398.45) 1(930.99,2398.45) 1(934.03,2355.37) 1(934.03,2355.37) 1(936.63,2172.81) 1(936.63,2172.81) 1(936.63,2207.05) 1(936.63,2207.05) 1(937.19,2282.81) 1(937.19,2282.81) 1(944.03,2375.69) 1(944.03,2375.69) 1(944.83,2356.29) 1(944.83,2356.29) 1(944.91,2172.81) 1(944.91,2172.81) 1(944.91,2207.05) 1(944.91,2207.05) 1(949.07,2375.17) 1(949.07,2375.17) 1(949.35,2351.17) 1(949.35,2351.17) 1(953.87,2207.05) 1(953.87,2207.05) 1(953.87,2213.81) 1(953.87,2213.81) 1(955.27,1729.45) 1(955.27,1729.45) 1(958.71,2352.89) 1(958.71,2352.89) 1(962.07,1616.98) 1(962.07,1736.25) 1(962.07,1736.25) 1(962.07,2348.29) 1(962.07,2348.29) 1(962.2,1736.25) 1(964.11,2351.09) 1(964.11,2351.09) 1(966.11,2347.45) 1(966.11,2347.45) 1(969,1729.45) 1(969,1729.45) 1(1007.87,2139.01) 1(1007.87,2139.01) 1(1007.87,2313.41) 1(1007.87,2313.41) 1(1007.99,2138.93) 1(1007.99,2138.93) 1(1007.99,2313.37) 1(1007.99,2313.37) 1(1015.47,2131.41) 1(1015.47,2131.41) 1(1015.47,2623.45) 1(1015.47,2623.45) 1(1051.93,1421.98) 1(1051.93,1421.98) 1(1059.46,1414.45) 1(1060.3,1414.45) 1(1060.3,1414.45) 1(1060.3,1564.45) 1(1067.83,1421.98) 1(1067.83,1421.98) 1(1078.31,-1645.55) 1(1078.31,-1645.55) 1(1078.31,-1145.55) 1(1078.31,-1145.55) 1(1166.3,1281.98) 1(1201.95,1281.98) 1(1201.95,1281.98) 1(1213.93,1218.45) 1(1222.48,1261.45) 1(1223.37,1209) 1(1223.37,1209) 1(1237.93,1209) 1(1247.61,-825.32) 1(1247.61,-798.23) 1(1247.61,-798.23) 1(1254.83,-791.02) 1(1311.83,-877.02) 1(1311.83,-862.02) 1(1311.83,-862.02) 1(1322.83,-851.02) 1(1322.83,-851.02) 1(1322.83,-805.02) 1(1322.83,-805.02) 1(1344.83,-783.02) 1(1474.83,852.98) 1(1487.83,852.98) 1(1487.83,852.98) 1(1502.83,1181.98) 1(1513.83,878.98) 1(1513.83,1181.98) 1(1559.83,836.84) 1(1567.7,844.7) 1(1567.7,844.7) 1(1604.55,844.7) 1(1604.55,844.7) 1(1606.93,1082.45) 1(1616.89,1072.48) 1(1616.89,1072.48) 1(1618.24,858.39) 1(1618.24,858.39) 1(1627.33,1072.48) 1(1627.33,1072.48) 1(1631.24,858.39) 1(1631.24,858.39) 1(1632.83,1002.98) 1(1642.83,1002.98) 1(1642.83,1002.98) 1(1643.83,1055.98) 1(1643.83,1055.98) 1(1648.83,875.98) 1(1648.83,875.98) 1(1648.83,900.98) 1(1655.06,538.5) 1(1664.83,1034.98) 1(1670.83,974.98) 1(1689.06,538.5) 1(1725.66,360.5) 1(1725.66,360.5) 1(1725.66,391.99) 1(1725.66,391.99) 1(1725.66,395.5) 1(1725.66,395.5) 1(1725.66,426.99) 1(1725.66,426.99) 1(1738.83,1239.98) 1(1741.73,230.98) 1(1741.73,244.95) 1(1745.83,1232.98) 1(1745.83,1232.98) 1(1746.19,360.5) 1(1746.19,391.99) 1(1746.19,395.5) 1(1746.19,426.99) 1(1764.19,360.5) 1(1764.19,391.99) 1(1764.19,395.5) 1(1764.19,426.99) 1(1784.71,360.5) 1(1784.71,360.5) 1(1784.71,391.99) 1(1784.71,391.99) 1(1784.71,395.5) 1(1784.71,395.5) 1(1784.71,426.99) 1(1784.71,426.99) 1(1784.83,1232.98) 1(1909.83,1616.98) 1(1916.83,1623.98) 1(1916.83,1623.98) 1(1922.83,1623.98) 1(1945.55,1296.97) 1(1945.55,1296.97) 1(1945.55,1317.5) 1(1945.55,1335.5) 1(1945.55,1356.02) 1(1945.55,1356.02) 1(1977.04,1296.97) 1(1977.04,1296.97) 1(1977.04,1317.5) 1(1977.04,1335.5) 1(1977.04,1356.02) 1(1977.04,1356.02) 1(1978.31,-1645.55) 1(1978.31,-1645.55) 1(1978.31,-1145.55) 1(1978.31,-1145.55) 1(2025.83,295.98) 1(2025.83,475.98) 1(2025.83,475.98) 1(2043.83,493.98) 1(2043.83,493.98) 1(2045.84,275.97) 1(2084.83,2771.98) 1(2086.83,536.98) 1(2086.83,545.98) 1(2089.73,232.85) 1(2094.83,237.98) 1(2094.83,237.98) 1(2096.83,2771.98) 1(2096.83,2771.98) 1(2104.83,2763.98) 1(2133.43,237.98) 1(2134.83,564.98) 1(2155.83,564.98) 1(2155.83,564.98) 1(2167.83,552.98) 1(2216.83,493.98) 1(2216.83,493.98) 1(2219.81,275.97) 1(2219.81,275.97) 1(2219.83,-531.02) 1(2219.83,-531.02) 1(2219.83,-325.02) 1(2219.83,-325.02) 1(2225.43,515.38) 1(2234.83,-546.02) 1(2234.83,-546.02) 1(2235.83,291.98) 1(2235.83,291.98) 1(2235.83,474.98) 1(2235.83,474.98) 1(2237.83,-307.02) 1(2237.83,-307.02) 1(2293.43,515.38) 1(2348.94,-266.02) 1(2360.83,959.98) 1(2360.83,959.98) 1(2360.83,989.98) 1(2384.33,936.48) 1(2401.39,921.7) 1(2401.39,921.7) 1(2401.39,953.2) 1(2401.39,953.2) 1(2412.72,-266.02) 1(2421.92,921.7) 1(2421.92,953.2) 1(2437.83,-307.02) 1(2437.83,-307.02) 1(2439.92,921.7) 1(2439.92,953.2) 1(2443.83,-546.02) 1(2443.83,-546.02) 1(2455.83,-534.02) 1(2455.83,-534.02) 1(2455.83,-325.02) 1(2455.83,-325.02) 1(2460.45,921.7) 1(2460.45,921.7) 1(2460.45,953.2) 1(2460.45,953.2)
  round 3.9 on Mech16: 1(219.77,-1397.03) 1(219.77,-1335.96) 1(219.77,-1199.28) 1(219.77,-1138.22) 1(219.77,-999.42) 1(219.77,-938.36) 1(280.83,-1397.03) 1(280.83,-1335.96) 1(280.83,-1199.28) 1(280.83,-1138.22) 1(280.83,-999.42) 1(280.83,-938.36) 1(362.03,441.74) 1(362.03,464.22) 1(362.03,500) 1(362.03,522.49) 1(369.94,441.74) 1(369.94,464.22) 1(369.94,500) 1(369.94,522.49) 1(376.4,-1119.08) 1(376.4,-1058.02) 1(381.71,441.74) 1(381.71,464.22) 1(381.71,500) 1(381.71,522.49) 1(389.62,441.74) 1(389.62,464.22) 1(389.62,500) 1(389.62,522.49) 1(401.4,441.74) 1(401.4,464.22) 1(401.4,500) 1(401.4,522.49) 1(409.31,441.74) 1(409.31,464.22) 1(409.31,500) 1(409.31,522.49) 1(437.46,-1119.08) 1(437.46,-1058.02) 1(526.4,-1341.08) 1(526.4,-1280.02) 1(587.46,-1341.08) 1(587.46,-1280.02) 1(869.03,1108.51) 1(869.03,1136.11) 1(869.03,1208.9) 1(869.03,1236.5) 1(886.78,1108.51) 1(886.78,1136.11) 1(886.78,1208.9) 1(886.78,1236.5) 1(906.43,1108.51) 1(906.43,1136.11) 1(906.43,1208.9) 1(906.43,1236.5) 1(917.03,-390.08) 1(917.03,-329.02) 1(924.18,1108.51) 1(924.18,1136.11) 1(924.18,1208.9) 1(924.18,1236.5) 1(943.83,1108.51) 1(943.83,1136.11) 1(943.83,1208.9) 1(943.83,1236.5) 1(961.58,1108.51) 1(961.58,1136.11) 1(961.58,1208.9) 1(961.58,1236.5) 1(978.09,-390.08) 1(978.09,-329.02) 1(1186.4,-1124.08) 1(1186.4,-1063.02) 1(1247.46,-1124.08) 1(1247.46,-1063.02) 1(1869.43,373.5) 1(1869.43,395.59) 1(1910.77,-807.03) 1(1910.77,-745.96) 1(1953.72,373.5) 1(1953.72,395.59) 1(1971.83,-807.03) 1(1971.83,-745.96) 1(2015.77,-1052.03) 1(2015.77,-990.96) 1(2076.83,-1052.03) 1(2076.83,-990.96)
  round 15.75 on Mech16: 1(405.35,469.32)
  round 157.48 on Mech16: 1(421.3,2233.5) 1(421.3,2981.54) 1(421.3,3300.21) 1(2350.43,2233.5) 1(2350.43,2981.54) 1(2350.43,3300.21)
  round 23.98 on Mech16: 1(505.83,933.96)
  round 19.68 on Mech16: 1(542.64,485.88) 1(710.18,659.74) 1(717.18,809.8) 1(793.92,333.85) 1(797.92,514.85) 1(1023.3,301.1) 1(1412.33,313.37) 1(2267.43,249.94)
  round 51 on Mech16: 1(640.43,2331.4) 1(640.43,3059.4) 1(1931.93,2331.4) 1(1931.93,3059.4)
